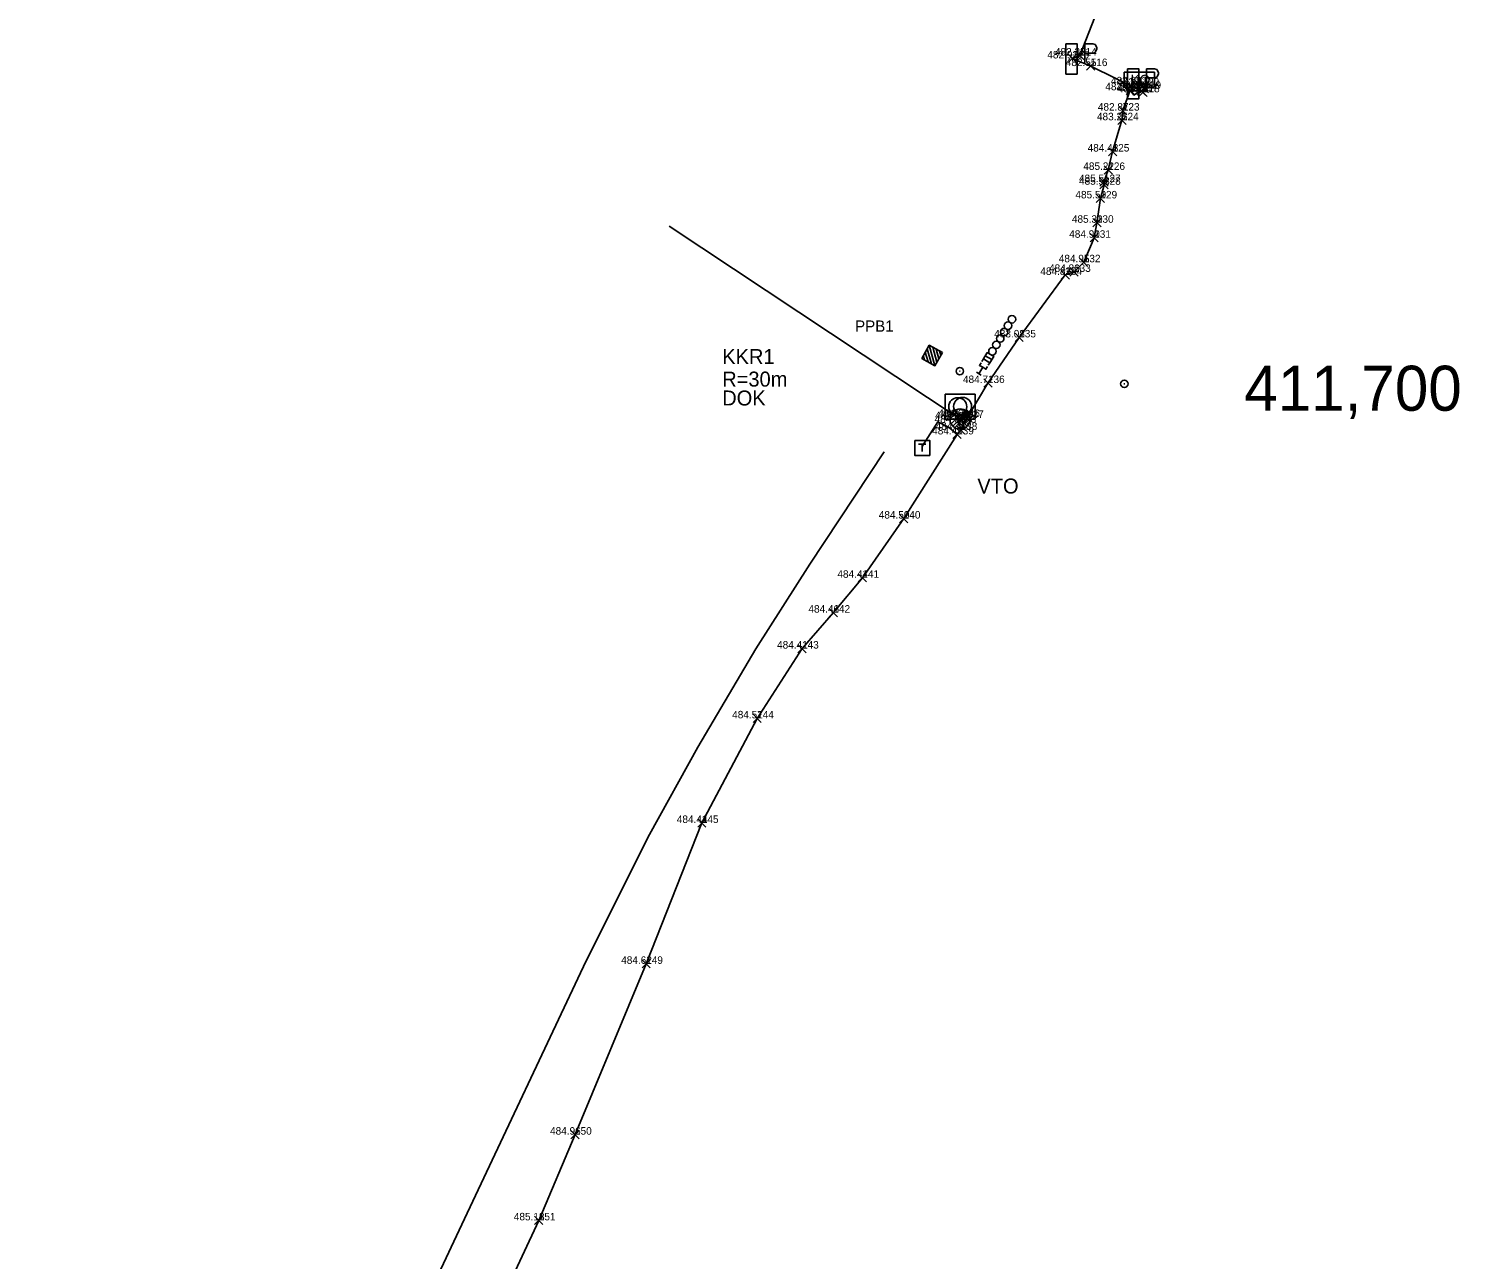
# Model space of a CAD drawing. Extents: x -874058 to -854960, y -10531873 to -1049126.
# Drawn here: x -867030 to -866839.2, y -1050944.1 to -1050780 of the extents above; entities that cross this region are included whole.
import ezdxf

# ---------------------------------------------------------------- set-up
doc = ezdxf.new("R2010")
doc.units = 0
for name, color, linetype in [('Vrstva 1', 7, 'Continuous'), ('Vrstva 25', 7, 'Continuous'), ('Vrstva 28', 7, 'Continuous'), ('Vrstva 3', 7, 'Continuous'), ('Vrstva 31', 7, 'Continuous'), ('Vrstva 32', 7, 'Continuous'), ('Vrstva 33', 7, 'Continuous'), ('Vrstva 35', 7, 'Continuous'), ('Vrstva 50', 7, 'Continuous'), ('Vrstva 6', 7, 'Continuous'), ('Vrstva 60', 7, 'Continuous'), ('Vrstva 61', 7, 'Continuous'), ('Vrstva 7', 7, 'Continuous')]:
    doc.layers.add(name, color=color, linetype=linetype)

msp = doc.modelspace()

# ---------------------------------------------------------------- linework, layer by layer
at = {"layer": 'Vrstva 1'}
for points in [[(-866933.01, -1050862.67), (-866925.79, -1050851.39), (-866915.87, -1050836.42)], [(-866933.01, -1050862.67), (-866940.75, -1050875.77), (-866947.17, -1050887.44), (-866955.62, -1050904.28), (-866971.87, -1050938.69), (-866984.17, -1050964.88), (-867009.17, -1051018.35), (-867029.98, -1051062.63)]]:
    msp.add_lwpolyline(points, dxfattribs=at)
at = {"layer": 'Vrstva 25'}
msp.add_lwpolyline([(-866882.84, -1050788.27), (-866882.84, -1050787.27), (-866880.84, -1050787.27), (-866880.84, -1050788.27), (-866882.84, -1050788.27)], dxfattribs=at)
at = {"layer": 'Vrstva 28'}
for p, q in [((-866879.83, -1050785.76), (-866883.87, -1050785.76)), ((-866883.87, -1050785.76), (-866883.87, -1050787.78)), ((-866879.83, -1050787.78), (-866879.83, -1050785.76)), ((-866883.87, -1050787.78), (-866879.83, -1050787.78))]:
    msp.add_line(p, q, dxfattribs=at)
msp.add_lwpolyline([(-866883.05, -1050788.18), (-866882.58, -1050788.83), (-866881.97, -1050788.44), (-866881.85, -1050787.78)], dxfattribs=at)
at = {"layer": 'Vrstva 3'}
for p, q in [((-866910.39, -1050823.12), (-866910.02, -1050824.4)), ((-866910.13, -1050822.66), (-866909.56, -1050824.66)), ((-866909.87, -1050822.19), (-866909.1, -1050824.91)), ((-866909.41, -1050822.45), (-866908.84, -1050824.45)), ((-866908.94, -1050822.71), (-866908.58, -1050823.99)), ((-866908.48, -1050822.97), (-866908.32, -1050823.52)), ((-866910.65, -1050823.58), (-866910.49, -1050824.14))]:
    msp.add_line(p, q, dxfattribs=at)
msp.add_lwpolyline([(-866908.12, -1050823.17), (-866909.1, -1050824.91), (-866910.84, -1050823.94), (-866909.87, -1050822.19)], close=True, dxfattribs=at)
msp.add_lwpolyline([(-866908.12, -1050823.17), (-866909.1, -1050824.91), (-866910.84, -1050823.94), (-866909.87, -1050822.19)], close=True, dxfattribs=at)
msp.add_lwpolyline([(-866908.12, -1050823.17), (-866909.1, -1050824.91), (-866910.84, -1050823.94), (-866909.87, -1050822.19), (-866908.12, -1050823.17)], dxfattribs=at)
msp.add_lwpolyline([(-866908.12, -1050823.17), (-866909.1, -1050824.91), (-866910.84, -1050823.94), (-866909.87, -1050822.19), (-866908.12, -1050823.17)], dxfattribs=at)
at = {"layer": 'Vrstva 31'}
for p, q in [((-866907.1, -1050832.03), (-866906.43, -1050831.36)), ((-866906.94, -1050832.68), (-866906.03, -1050831.76)), ((-866905.53, -1050832.25), (-866904.61, -1050831.33)), ((-866905.12, -1050832.66), (-866904.41, -1050831.95)), ((-866904.8, -1050831.07), (-866904.8, -1050831.07)), ((-866904.8, -1050831.07), (-866904.8, -1050831.07)), ((-866906.72, -1050832.98), (-866906.72, -1050832.98)), ((-866906.72, -1050832.98), (-866906.72, -1050832.98)), ((-866904.8, -1050832.98), (-866904.8, -1050832.98))]:
    msp.add_line(p, q, dxfattribs=at)
for points in [[(-866906.71, -1050831.07), (-866905.76, -1050832.03), (-866906.72, -1050832.98)], [(-866904.8, -1050831.07), (-866905.75, -1050832.03), (-866904.8, -1050832.98)]]:
    msp.add_lwpolyline(points, dxfattribs=at)
for centre, start, end in [((-866905.75, -1050832.03), 45.4761, 134.8422), ((-866905.76, -1050832.03), 134.5239, 224.7609), ((-866905.75, -1050832.03), 315.2391, 45.4761), ((-866905.76, -1050832.03), 224.7623, 315.5517)]:
    msp.add_arc(centre, 1.35, start, end, dxfattribs=at)
at = {"layer": 'Vrstva 32'}
msp.add_line((-866905.83, -1050829.21), (-866905.78, -1050829.22), dxfattribs=at)
for points in [[(-866844.73, -1050675.55), (-866847.88, -1050678.64), (-866854.48, -1050695.91), (-866859.41, -1050709.3), (-866866.58, -1050727.75), (-866871.36, -1050740.38), (-866873.68, -1050743.97), (-866875.66, -1050748.85), (-866883.51, -1050768.17), (-866887.4, -1050777.39), (-866889.77, -1050783.55), (-866890.79, -1050783.93), (-866888.33, -1050784.95), (-866881.57, -1050788.3)], [(-866881.37, -1050788.45), (-866881.18, -1050787.98), (-866881.44, -1050787.55), (-866882.31, -1050787.39), (-866883.05, -1050788.18), (-866884.05, -1050790.89), (-866884.17, -1050792.18), (-866885.41, -1050796.35), (-866885.99, -1050798.8), (-866886.57, -1050800.43), (-866886.56, -1050800.78), (-866887.04, -1050802.6), (-866887.51, -1050805.85), (-866887.87, -1050807.85), (-866889.26, -1050811.12)], [(-866889.26, -1050811.12), (-866890.56, -1050812.4), (-866891.72, -1050812.81)], [(-866891.72, -1050812.81), (-866897.87, -1050821.14), (-866902.04, -1050827.23), (-866904.83, -1050831.88)], [(-866904.83, -1050831.88), (-866905.69, -1050833.48), (-866906.15, -1050834.08), (-866913.27, -1050845.3), (-866918.79, -1050853.2), (-866922.65, -1050857.85), (-866926.83, -1050862.64), (-866932.82, -1050871.95), (-866940.2, -1050885.9)], [(-866906.15, -1050834.08), (-866907.22, -1050833.17), (-866908.7, -1050832.38), (-866910.78, -1050835.61), (-866910.81, -1050835.87)], [(-866904.83, -1050831.88), (-866905.34, -1050831.75), (-866905.75, -1050832.03), (-866905.83, -1050832.53), (-866905.69, -1050833.48)], [(-866940.2, -1050885.9), (-866947.62, -1050904.69), (-866957.11, -1050927.47), (-866961.94, -1050938.9), (-866966.36, -1050948.45), (-866968.85, -1050953.26), (-866970.55, -1050955.61), (-866975.35, -1050958.71), (-866976.76, -1050959.98), (-866979.92, -1050967.6)]]:
    msp.add_lwpolyline(points, dxfattribs=at)
msp.add_lwpolyline([(-866907.74, -1050828.71), (-866903.76, -1050828.71), (-866903.76, -1050832.03), (-866907.74, -1050832.03)], close=True, dxfattribs=at)
for centre in [(-866906.07, -1050830.38), (-866905.41, -1050830.35)]:
    msp.add_circle(centre, 1.2, dxfattribs=at)
at = {"layer": 'Vrstva 33'}
for p, q in [((-866911.31, -1050835.37), (-866910.31, -1050835.37)), ((-866910.81, -1050835.37), (-866910.81, -1050836.37))]:
    msp.add_line(p, q, dxfattribs=at)
for points in [[(-866891.64, -1050781.98), (-866890.15, -1050781.98), (-866890.15, -1050786.01), (-866891.64, -1050786.01)], [(-866883.42, -1050785.31), (-866881.93, -1050785.31), (-866881.93, -1050789.34), (-866883.42, -1050789.34)]]:
    msp.add_lwpolyline(points, close=True, dxfattribs=at)
for points in [[(-866889.1, -1050784.48), (-866889.1, -1050781.97)], [(-866889.1, -1050781.97), (-866888.06, -1050781.97)], [(-866888.06, -1050781.97), (-866887.74, -1050782.07), (-866887.52, -1050782.48), (-866887.52, -1050782.7), (-866887.74, -1050783.12), (-866888.06, -1050783.21)], [(-866888.06, -1050783.21), (-866889.1, -1050783.21)], [(-866880.88, -1050787.81), (-866880.88, -1050785.3)], [(-866880.88, -1050785.3), (-866879.84, -1050785.3)], [(-866879.84, -1050786.54), (-866880.88, -1050786.54)], [(-866879.84, -1050785.3), (-866879.53, -1050785.4), (-866879.3, -1050785.81), (-866879.3, -1050786.03), (-866879.53, -1050786.45), (-866879.84, -1050786.54)], [(-866911.81, -1050834.87), (-866909.81, -1050834.87), (-866909.81, -1050836.87), (-866911.81, -1050836.87), (-866911.81, -1050834.87)]]:
    msp.add_lwpolyline(points, dxfattribs=at)
at = {"layer": 'Vrstva 35'}
for points in [[(-866881.57, -1050788.3), (-866888.33, -1050784.95)], [(-866883.05, -1050788.18), (-866884.05, -1050790.89), (-866884.17, -1050792.18)], [(-866891.72, -1050812.81), (-866897.87, -1050821.14)]]:
    msp.add_lwpolyline(points, dxfattribs=at)
at = {"layer": 'Vrstva 50'}
msp.add_line((-866905.84, -1050825.64), (-866905.74, -1050825.64), dxfattribs=at)
msp.add_circle((-866905.79, -1050825.64), 0.5, dxfattribs=at)
at = {"layer": 'Vrstva 6'}
for p, q in [((-866902.39, -1050823.58), (-866901.53, -1050824.1)), ((-866903.58, -1050825.79), (-866902.94, -1050826.17)), ((-866903.26, -1050825.98), (-866903.26, -1050825.98)), ((-866903.26, -1050825.98), (-866903.26, -1050825.98))]:
    msp.add_line(p, q, dxfattribs=at)
for points in [[(-866902.22, -1050824.27), (-866901.79, -1050824.53), (-866901.27, -1050823.68), (-866902.13, -1050823.16), (-866902.65, -1050824.01), (-866902.22, -1050824.27)], [(-866903.26, -1050825.98), (-866902.74, -1050825.13), (-866902.31, -1050825.39), (-866902.11, -1050825.04)], [(-866902.96, -1050824.52), (-866903.17, -1050824.87), (-866902.74, -1050825.13)], [(-866901.99, -1050824.86), (-866901.79, -1050824.53), (-866902.65, -1050824.01), (-866902.85, -1050824.34)]]:
    msp.add_lwpolyline(points, dxfattribs=at)
for centre in [(-866899.36, -1050819.57), (-866898.84, -1050818.72), (-866900.4, -1050821.28), (-866899.88, -1050820.43), (-866901.44, -1050822.99), (-866900.92, -1050822.13)]:
    msp.add_circle(centre, 0.5, dxfattribs=at)
at = {"layer": 'Vrstva 60'}
for p, q in [((-866890.32, -1050784.1), (-866889.22, -1050783)), ((-866889.22, -1050784.1), (-866890.32, -1050783)), ((-866891.34, -1050784.48), (-866890.24, -1050783.38)), ((-866890.24, -1050784.48), (-866891.34, -1050783.38)), ((-866888.88, -1050785.5), (-866887.78, -1050784.4)), ((-866887.78, -1050785.5), (-866888.88, -1050784.4)), ((-866882.86, -1050787.94), (-866881.76, -1050786.84)), ((-866881.76, -1050787.94), (-866882.86, -1050786.84)), ((-866883.6, -1050788.73), (-866882.5, -1050787.63)), ((-866882.5, -1050788.73), (-866883.6, -1050787.63)), ((-866882.12, -1050788.85), (-866881.02, -1050787.75)), ((-866881.02, -1050788.85), (-866882.12, -1050787.75)), ((-866881.99, -1050788.1), (-866880.89, -1050787)), ((-866880.89, -1050788.1), (-866881.99, -1050787)), ((-866881.92, -1050789), (-866880.82, -1050787.9)), ((-866880.82, -1050789), (-866881.92, -1050787.9)), ((-866881.73, -1050788.53), (-866880.63, -1050787.43)), ((-866880.63, -1050788.53), (-866881.73, -1050787.43)), ((-866884.6, -1050791.44), (-866883.5, -1050790.34)), ((-866883.5, -1050791.44), (-866884.6, -1050790.34)), ((-866884.72, -1050792.73), (-866883.62, -1050791.63)), ((-866883.62, -1050792.73), (-866884.72, -1050791.63)), ((-866885.96, -1050796.9), (-866884.86, -1050795.8)), ((-866884.86, -1050796.9), (-866885.96, -1050795.8)), ((-866886.54, -1050799.35), (-866885.44, -1050798.25)), ((-866885.44, -1050799.35), (-866886.54, -1050798.25)), ((-866887.12, -1050800.98), (-866886.02, -1050799.88)), ((-866886.02, -1050800.98), (-866887.12, -1050799.88)), ((-866887.11, -1050801.33), (-866886.01, -1050800.23)), ((-866886.01, -1050801.33), (-866887.11, -1050800.23)), ((-866887.59, -1050803.15), (-866886.49, -1050802.05)), ((-866886.49, -1050803.15), (-866887.59, -1050802.05)), ((-866888.06, -1050806.4), (-866886.96, -1050805.3)), ((-866886.96, -1050806.4), (-866888.06, -1050805.3)), ((-866888.42, -1050808.4), (-866887.32, -1050807.3)), ((-866887.32, -1050808.4), (-866888.42, -1050807.3)), ((-866889.81, -1050811.67), (-866888.71, -1050810.57)), ((-866888.71, -1050811.67), (-866889.81, -1050810.57)), ((-866892.27, -1050813.36), (-866891.17, -1050812.26)), ((-866891.17, -1050813.36), (-866892.27, -1050812.26)), ((-866891.11, -1050812.95), (-866890.01, -1050811.85)), ((-866890.01, -1050812.95), (-866891.11, -1050811.85)), ((-866898.42, -1050821.69), (-866897.32, -1050820.59)), ((-866897.32, -1050821.69), (-866898.42, -1050820.59)), ((-866902.59, -1050827.78), (-866901.49, -1050826.68)), ((-866901.49, -1050827.78), (-866902.59, -1050826.68)), ((-866906.38, -1050833.08), (-866905.28, -1050831.98)), ((-866905.28, -1050833.08), (-866906.38, -1050831.98)), ((-866906.3, -1050832.58), (-866905.2, -1050831.48)), ((-866905.2, -1050832.58), (-866906.3, -1050831.48)), ((-866905.89, -1050832.3), (-866904.79, -1050831.2)), ((-866904.79, -1050832.3), (-866905.89, -1050831.2)), ((-866905.38, -1050832.43), (-866904.28, -1050831.33)), ((-866904.28, -1050832.43), (-866905.38, -1050831.33)), ((-866906.7, -1050834.63), (-866905.6, -1050833.53)), ((-866905.6, -1050834.63), (-866906.7, -1050833.53)), ((-866906.24, -1050834.03), (-866905.14, -1050832.93)), ((-866905.14, -1050834.03), (-866906.24, -1050832.93)), ((-866913.82, -1050845.85), (-866912.72, -1050844.75)), ((-866912.72, -1050845.85), (-866913.82, -1050844.75)), ((-866919.34, -1050853.75), (-866918.24, -1050852.65)), ((-866918.24, -1050853.75), (-866919.34, -1050852.65)), ((-866923.2, -1050858.4), (-866922.1, -1050857.3)), ((-866922.1, -1050858.4), (-866923.2, -1050857.3)), ((-866927.38, -1050863.19), (-866926.28, -1050862.09)), ((-866926.28, -1050863.19), (-866927.38, -1050862.09)), ((-866933.37, -1050872.5), (-866932.27, -1050871.4)), ((-866932.27, -1050872.5), (-866933.37, -1050871.4)), ((-866940.75, -1050886.45), (-866939.65, -1050885.35)), ((-866939.65, -1050886.45), (-866940.75, -1050885.35)), ((-866948.17, -1050905.24), (-866947.07, -1050904.14)), ((-866947.07, -1050905.24), (-866948.17, -1050904.14)), ((-866957.66, -1050928.02), (-866956.56, -1050926.92)), ((-866956.56, -1050928.02), (-866957.66, -1050926.92)), ((-866962.49, -1050939.45), (-866961.39, -1050938.35)), ((-866961.39, -1050939.45), (-866962.49, -1050938.35))]:
    msp.add_line(p, q, dxfattribs=at)
at = {"layer": 'Vrstva 7'}
for p, q in [((-866944.54, -1050806.32), (-866905.75, -1050832.03)), ((-866883.9, -1050827.33), (-866883.8, -1050827.33))]:
    msp.add_line(p, q, dxfattribs=at)
msp.add_circle((-866883.85, -1050827.33), 0.5, dxfattribs=at)

# ---------------------------------------------------------------- texts
at = {"layer": 'Vrstva 28'}
msp.add_text('KO', height=1.344, dxfattribs=at).set_placement((-866883, -1050787.46))
at = {"layer": 'Vrstva 3'}
msp.add_text('PPB1', height=1.5, dxfattribs=at).set_placement((-866919.75, -1050820.38))
at = {"layer": 'Vrstva 32'}
for s, p in [('KKR1', (-866937.48, -1050824.69)), ('R=30m', (-866937.48, -1050827.7)), ('DOK', (-866937.48, -1050830.22)), ('VTO', (-866903.45, -1050841.96))]:
    msp.add_text(s, height=2, dxfattribs=at).set_placement(p)
at = {"layer": 'Vrstva 60'}
for s, p in [('115', (-866890.79, -1050783.93)), ('114', (-866889.77, -1050783.55)), ('116', (-866888.33, -1050784.95)), ('121', (-866882.31, -1050787.39)), ('120', (-866881.44, -1050787.55)), ('122', (-866883.05, -1050788.18)), ('117', (-866881.57, -1050788.3)), ('118', (-866881.37, -1050788.45)), ('119', (-866881.18, -1050787.98)), ('123', (-866884.05, -1050790.89)), ('124', (-866884.17, -1050792.18)), ('125', (-866885.41, -1050796.35)), ('126', (-866885.99, -1050798.8)), ('127', (-866886.57, -1050800.43)), ('128', (-866886.56, -1050800.78)), ('129', (-866887.04, -1050802.6)), ('130', (-866887.51, -1050805.85)), ('131', (-866887.87, -1050807.85)), ('133', (-866890.56, -1050812.4)), ('132', (-866889.26, -1050811.12)), ('134', (-866891.72, -1050812.81)), ('135', (-866897.87, -1050821.14)), ('136', (-866902.04, -1050827.23)), ('146', (-866905.34, -1050831.75)), ('148', (-866905.83, -1050832.53)), ('147', (-866905.75, -1050832.03)), ('138', (-866905.69, -1050833.48)), ('137', (-866904.83, -1050831.88)), ('139', (-866906.15, -1050834.08)), ('140', (-866913.27, -1050845.3)), ('141', (-866918.79, -1050853.2)), ('142', (-866922.65, -1050857.85)), ('143', (-866926.83, -1050862.64)), ('144', (-866932.82, -1050871.95)), ('145', (-866940.2, -1050885.9)), ('149', (-866947.62, -1050904.69)), ('150', (-866957.11, -1050927.47)), ('151', (-866961.94, -1050938.9))]:
    msp.add_text(s, height=1, dxfattribs=at).set_placement(p)
at = {"layer": 'Vrstva 61'}
for s, p in [('482.92 ', (-866894.12, -1050783.93)), ('482.35 ', (-866893.1, -1050783.55)), ('482.55 ', (-866891.66, -1050784.95)), ('482.98 ', (-866885.64, -1050787.39)), ('483.14 ', (-866884.77, -1050787.55)), ('482.99 ', (-866886.38, -1050788.18)), ('482.69 ', (-866884.9, -1050788.3)), ('483.03 ', (-866884.7, -1050788.45)), ('483.09 ', (-866884.51, -1050787.98)), ('482.87 ', (-866887.38, -1050790.89)), ('483.25 ', (-866887.5, -1050792.18)), ('484.48 ', (-866888.74, -1050796.35)), ('485.22 ', (-866889.32, -1050798.8)), ('485.51 ', (-866889.9, -1050800.43)), ('485.53 ', (-866889.89, -1050800.78)), ('485.50 ', (-866890.37, -1050802.6)), ('485.30 ', (-866890.84, -1050805.85)), ('484.90 ', (-866891.2, -1050807.85)), ('484.86 ', (-866893.89, -1050812.4)), ('484.95 ', (-866892.59, -1050811.12)), ('484.83 ', (-866895.05, -1050812.81)), ('483.08 ', (-866901.2, -1050821.14)), ('484.71 ', (-866905.37, -1050827.23)), ('484.62 ', (-866908.67, -1050831.75)), ('484.63 ', (-866909.16, -1050832.53)), ('485.04 ', (-866909.08, -1050832.03)), ('484.76 ', (-866909.02, -1050833.48)), ('484.50 ', (-866908.16, -1050831.88)), ('484.49 ', (-866909.48, -1050834.08)), ('484.50 ', (-866916.6, -1050845.3)), ('484.44 ', (-866922.12, -1050853.2)), ('484.46 ', (-866925.98, -1050857.85)), ('484.41 ', (-866930.16, -1050862.64)), ('484.57 ', (-866936.15, -1050871.95)), ('484.44 ', (-866943.53, -1050885.9)), ('484.62 ', (-866950.95, -1050904.69)), ('484.96 ', (-866960.44, -1050927.47)), ('485.18 ', (-866965.27, -1050938.9))]:
    msp.add_text(s, height=1, dxfattribs=at).set_placement(p)
at = {"layer": 'Vrstva 7'}
msp.add_text('411,700', height=6, dxfattribs=at).set_placement((-866867.85, -1050830.92))

doc.saveas('drawing.dxf')
